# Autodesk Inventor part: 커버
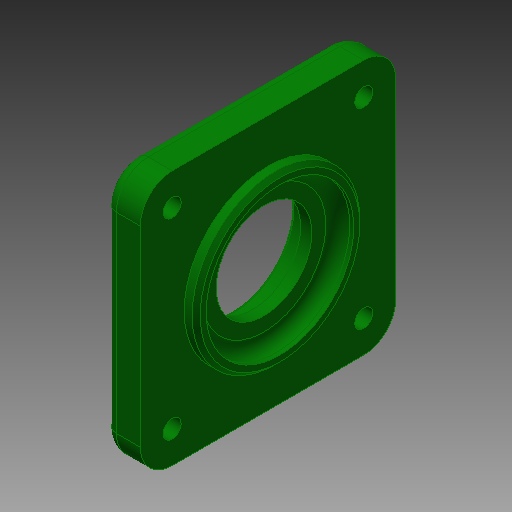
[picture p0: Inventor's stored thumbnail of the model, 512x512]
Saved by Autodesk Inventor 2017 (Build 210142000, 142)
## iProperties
Created: 2019-09
Part Number: 커버
Material: 알루미늄 6061
Document SubType Name: Modeling
Designer: mduedu
Density: 2.71 g/cm^3
Appearance: 진녹색
Mass: 80.7314 g
Surface Area: 109.271 cm^2
Volume: 29.7902 cm^3
Author: mduedu
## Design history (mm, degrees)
sketch "스케치1"
  geometry: L1 (-32, -32)-(32, -32); L2 (32, -32)-(32, 32); L3 (32, 32)-(-32, 32); L4 (-32, 32)-(-32, -32); L5 (-32, -32)-(32, 32); L6 (32, -32)-(-32, 32); 1 further point
  constraints: 12 end point, 2 midpoint, 2 parallel, 1 horizontal, 1 perpendicular
  dimensions: "d44" = 64 distance of L3.end L2.end; "d45" = 64 distance of L2.end L1.end
extrude "돌출1" new body sketch "스케치1" distance "d1" = 9; taper "d2" = 0 deg
sketch "스케치2"
  geometry: C1 r 21 at (0, 0); 1 further point
  constraints: 1 centre point, 1 coincident
  dimensions: "d3" = 42 diameter of C1
extrude "돌출2" join sketch "스케치2" distance "d4" = 3; taper "d5" = 0 deg
hole "구멍1" diameter "d8" = 24; stored, may be unused: countersink angle "d12" = 90 deg, drill point angle "d14" = 118 deg; dims "d9" = 6, "d10" = 30, "d11" = 5.2, "d13" = 8, "d46" = 10, "d47" = 10
hole "구멍2" diameter "d17" = 37; stored, may be unused: countersink angle "d21" = 90 deg, drill point angle "d23" = 0 deg; dims "d15" = 10, "d16" = 10, "d18" = 6, "d19" = 30, "d20" = 5.2, "d22" = 4
fillet "모깎기1" dims "d24" = 3
fillet "모깎기4" dims "d48" = 8
fillet "모깎기2" dims "d25" = 3
chamfer "모따기1" distance "d27" = 0.5; stored, may be unused: second distance "d28" = 2, angle "d29" = 30 deg
chamfer "모따기2" distance "d30" = 1; stored, may be unused: second distance "d31" = 2, angle "d32" = 30 deg
sketch "스케치4"
  geometry: A1 r 8 centre (-24, 24) between (-24, 32) and (-32, 24) reference; A2 r 8 centre (24, 24) between (32, 24) and (24, 32) reference; A3 r 8 centre (24, -24) between (24, -32) and (32, -24) reference; A4 r 8 centre (-24, -24) between (-32, -24) and (-24, -32) reference; 5 further points
  constraints: 4 coincident
hole "구멍4" sketch "스케치4" at (-24, 24), (24, 24), (24, -24), (-24, -24) diameter "d49" = 4.5; stored, may be unused: countersink angle "d53" = 90 deg, drill point angle "d55" = 118 deg; dims "d50" = 6, "d51" = 8, "d52" = 4.4, "d54" = 8
node "솔리드1"
